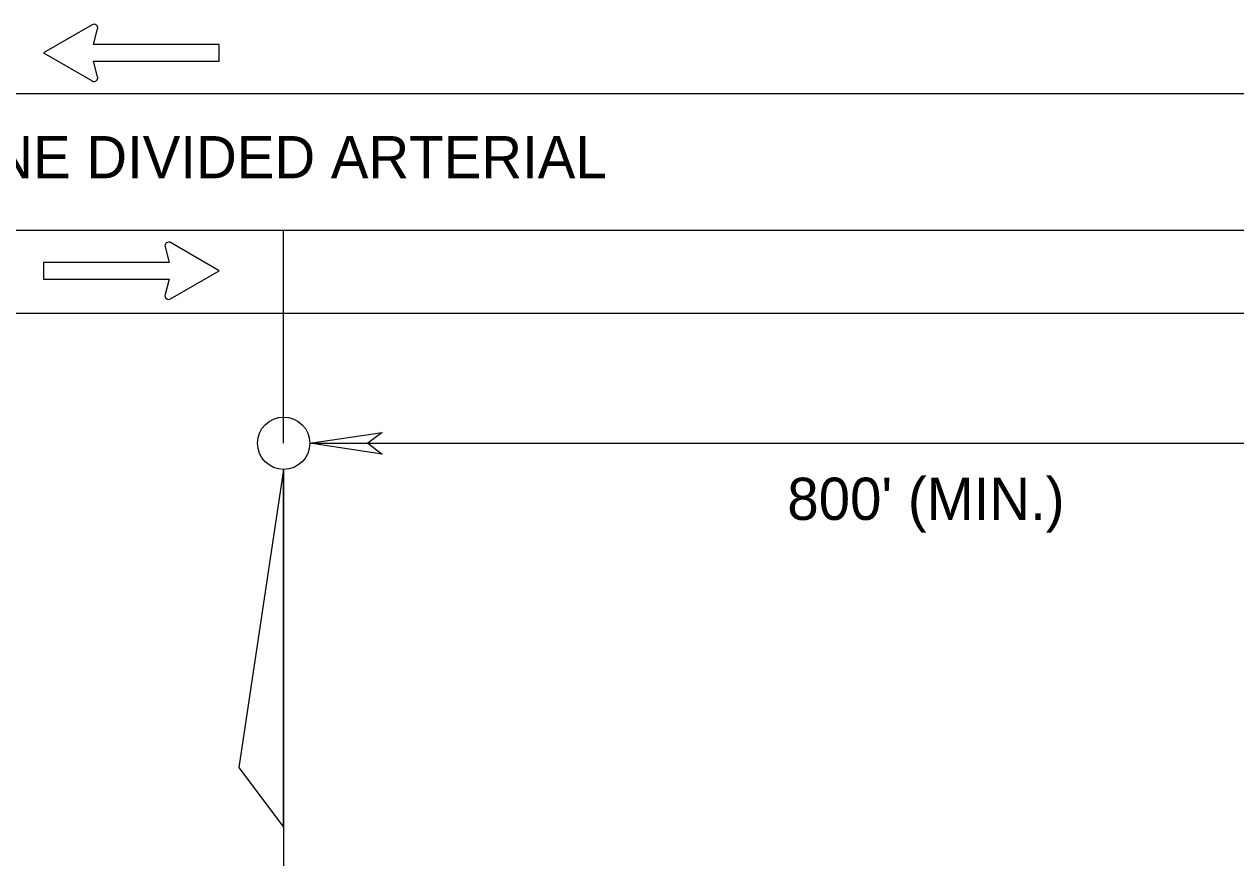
# Model space of a CAD drawing. Extents: x -830008.4 to -829992.7, y 1290284.1 to 1290294.4.
# Drawn here: x -830005.685 to -830003.674, y 1290288.617 to 1290289.999 of the extents above; entities that cross this region are included whole.
import ezdxf

# ---------------------------------------------------------------- set-up
doc = ezdxf.new("R2010")
doc.units = 0
for name, color, linetype in [('LaneDirArrow', 7, 'Continuous'), ('LeaderLine_dp', 7, 'Continuous'), ('SignTruss', 7, 'Continuous'), ('TextLabel', 7, 'Continuous')]:
    doc.layers.add(name, color=color, linetype=linetype)

msp = doc.modelspace()

# ---------------------------------------------------------------- linework, layer by layer
at = {"layer": 'LaneDirArrow'}
for p, q in [((-830005.5718, 1290289.9986), (-830005.6526, 1290289.952)), ((-830005.5695, 1290289.9659), (-830005.5627, 1290289.9916)), ((-830005.6526, 1290289.952), (-830005.5718, 1290289.9054)), ((-830005.3609, 1290289.9659), (-830005.5695, 1290289.9659)), ((-830005.3609, 1290289.9381), (-830005.3609, 1290289.9659)), ((-830005.5695, 1290289.9381), (-830005.3609, 1290289.9381)), ((-830005.5627, 1290289.9124), (-830005.5695, 1290289.9381)), ((-830005.4508, 1290289.6301), (-830005.4439, 1290289.6044)), ((-830005.3609, 1290289.5905), (-830005.4417, 1290289.6372)), ((-830005.4439, 1290289.6044), (-830005.6526, 1290289.6044)), ((-830005.6526, 1290289.6044), (-830005.6526, 1290289.5767)), ((-830005.4417, 1290289.5439), (-830005.3609, 1290289.5905)), ((-830005.6526, 1290289.5767), (-830005.4439, 1290289.5767)), ((-830005.4439, 1290289.5767), (-830005.4508, 1290289.551))]:
    msp.add_line(p, q, dxfattribs=at)
for centre, start, end in [((-830005.5687, 1290289.9932), 345, 120), ((-830005.5687, 1290289.9108), 240, 15), ((-830005.4448, 1290289.6318), 60, 195), ((-830005.4448, 1290289.5493), 165, 300)]:
    msp.add_arc(centre, 0.00625, start, end, dxfattribs=at)
at = {"layer": 'LeaderLine_dp'}
for p, q in [((-830005.2106, 1290289.3045), (-830005.0906, 1290289.3225)), ((-830005.0906, 1290289.3225), (-830005.1146, 1290289.3045)), ((-830005.0906, 1290289.2865), (-830005.2106, 1290289.3045)), ((-830005.1146, 1290289.3045), (-830005.0906, 1290289.2865)), ((-830005.2541, 1290289.261), (-830005.3283, 1290288.7665)), ((-830005.2541, 1290288.6676), (-830005.2541, 1290289.261)), ((-830005.3283, 1290288.7665), (-830005.2541, 1290288.6676))]:
    msp.add_line(p, q, dxfattribs=at)
at = {"layer": 'SignTruss'}
msp.add_line((-830005.2541, 1290289.3045), (-830005.2541, 1290289.6579), dxfattribs=at)
msp.add_circle((-830005.2541, 1290289.3045), 0.0434, dxfattribs=at)
at = {"layer": 'TextLabel'}
for p, q in [((-830001.5198, 1290289.8838), (-830007.4742, 1290289.8838)), ((-830007.4742, 1290289.6579), (-830003.5393, 1290289.6579)), ((-830007.4742, 1290289.5202), (-830003.5393, 1290289.5202)), ((-830005.2106, 1290289.3045), (-830002.9806, 1290289.3045)), ((-830005.2541, 1290289.261), (-830005.2541, 1290287.8659))]:
    msp.add_line(p, q, dxfattribs=at)

# ---------------------------------------------------------------- texts
for s, p in [('TYPICAL MULTI-LANE DIVIDED ARTERIAL', (-830006.5802, 1290289.7439)), ("800' (MIN.)", (-830004.4185, 1290289.1773))]:
    msp.add_text(s, height=0.07, rotation=0.0044, dxfattribs=at).set_placement(p)

doc.saveas('drawing.dxf')
